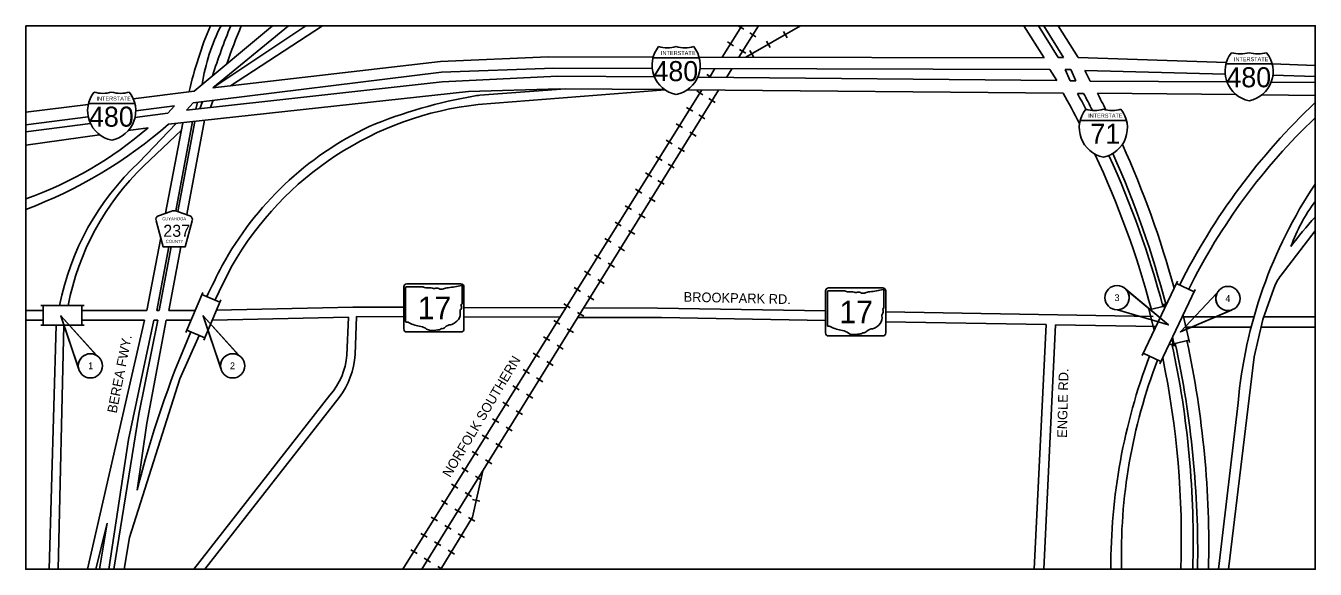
# Model space of a CAD drawing. Extents: x 0 to 1336, y 0 to 440.
# Drawn here: x 800 to 1336, y 188 to 413 of the extents above; entities that cross this region are included whole.
import ezdxf

# ---------------------------------------------------------------- set-up
doc = ezdxf.new("R2010")
doc.units = 0
for name, color, linetype in [('SH_Text', 7, 'Continuous'), ('SN_P_Text', 7, 'Continuous'), ('SN_X_Public', 7, 'Continuous')]:
    doc.layers.add(name, color=color, linetype=linetype)

msp = doc.modelspace()

# ---------------------------------------------------------------- linework, layer by layer
at = {"layer": 'SH_Text'}
for points in [[(1257.31, 303.98), (1274.97, 289.23), (1253.77, 295.49)], [(1301.11, 295.35), (1279.95, 286.31), (1295.15, 302.36)], [(821.92, 271.19), (814.58, 293), (829.38, 276.58)], [(881.02, 271.19), (873.69, 293), (888.48, 276.58)]]:
    msp.add_lwpolyline(points, dxfattribs=at)
for centre, major_axis in [((1253.63, 300.53), (3.65, 3.48)), ((1299.7, 300.2), (1.45, -4.83)), ((826.85, 272.21), (-4.93, -1.06)), ((885.96, 272.21), (-4.93, -1.06))]:
    msp.add_ellipse(centre, major_axis=major_axis, ratio=0.999122, start_param=3.977083, end_param=6.275668, dxfattribs=at)
at = {"layer": 'SN_P_Text'}
for p, q in [((869.93, 386.39), (902.5, 413.48)), ((877.75, 387.74), (909.24, 413.48)), ((916.35, 413.48), (877.75, 387.74)), ((885.07, 388.58), (923.29, 413.48)), ((1089.44, 400.45), (1097.57, 413.48)), ((1096.1, 413.48), (1098.45, 412.03)), ((1096.44, 400.43), (1104.53, 413.48)), ((1122.07, 413.48), (1099.23, 400.42)), ((1223.25, 400.11), (1214.87, 413.48)), ((1229.17, 400.32), (1220.91, 413.48)), ((1231.39, 400.32), (1223.13, 413.48)), ((1237.39, 400.32), (1229.13, 413.48)), ((1100.91, 410.5), (1103.51, 408.89)), ((1114.91, 411.14), (1116.43, 408.5)), ((1091.62, 406.82), (1094.21, 405.22)), ((1096.67, 403.69), (1099.26, 402.09)), ((1100.98, 403.18), (1102.5, 400.54)), ((1107.95, 407.16), (1109.47, 404.52)), ((877.75, 387.74), (972.38, 398.63)), ((972.38, 398.63), (1017.15, 400.63)), ((1017.15, 400.63), (1060.81, 400.52)), ((1079.87, 400.47), (1223.25, 400.11)), ((1231.39, 400.32), (1229.17, 400.32)), ((1237.39, 400.32), (1299.06, 398.27)), ((1318.11, 397.63), (1335.98, 397.04)), ((869.63, 381.53), (972.73, 394.16)), ((972.73, 394.16), (1019.53, 395.9)), ((1020.96, 392.6), (973.04, 390.21)), ((1019.53, 395.9), (1060.41, 395.77)), ((1020.96, 392.6), (1061.32, 392.25)), ((1079.28, 392.1), (1228.52, 390.81)), ((1080.25, 395.71), (1225.73, 395.26)), ((1083.13, 393.21), (1085, 392.05)), ((1084.2, 392.05), (1086.47, 395.69)), ((1091.21, 391.99), (1093.49, 395.67)), ((1228.52, 390.81), (1225.73, 395.26)), ((1234.16, 390.66), (1231.98, 395.26)), ((1231.98, 395.26), (1234.33, 395.26)), ((1236.51, 390.66), (1234.33, 395.26)), ((1240.18, 394.94), (1298.54, 393.43)), ((1240.18, 394.94), (1242.48, 390.54)), ((1318.39, 392.92), (1335.98, 392.46)), ((844.64, 383.2), (869.93, 386.39)), ((859.35, 372.58), (984, 386.12)), ((973.04, 390.21), (866.77, 378.43)), ((956.78, 187.73), (1080.94, 386.82)), ((964.61, 187.73), (1087.97, 386.76)), ((984, 386.12), (1021.85, 387.33)), ((988.1, 380.77), (1065.7, 386.85)), ((988.7, 384.61), (1024.39, 387.3)), ((1021.85, 387.33), (1065.56, 386.95)), ((1074.99, 386.87), (1231.16, 385.52)), ((1078.88, 386.4), (1081.47, 384.8)), ((1236.51, 390.66), (1234.16, 390.66)), ((1242.48, 390.54), (1299.3, 390.14)), ((1317.64, 390.02), (1335.98, 389.89)), ((799.98, 377.57), (825.97, 380.84)), ((866.77, 378.43), (869.63, 381.53)), ((870.66, 378.86), (871.4, 381.75)), ((872.29, 379.04), (873.42, 381.99)), ((876.83, 379.55), (877.88, 382.54)), ((1083.95, 383.26), (1086.54, 381.65)), ((1237.14, 385.38), (1239.7, 385.41)), ((1303.07, 384.89), (1245.42, 385.48)), ((1335.98, 384.55), (1313.78, 384.78)), ((825.95, 375.62), (799.98, 372.28)), ((845.36, 375.35), (858.97, 377.13)), ((861.83, 380.22), (845.69, 378.15)), ((858.97, 377.13), (861.83, 380.22)), ((1074.64, 379.59), (1077.23, 377.99)), ((1079.71, 376.45), (1082.3, 374.85)), ((799.98, 369.43), (826.84, 372.94)), ((850.81, 371.13), (842.6, 369.96)), ((847.04, 356.75), (862.48, 372.92)), ((849.08, 355.36), (864.68, 370.08)), ((858.04, 335.6), (865.29, 373.23)), ((862.31, 336.59), (869.32, 373.67)), ((863.18, 336.36), (870.25, 373.77)), ((866.91, 335.02), (874.32, 374.21)), ((1070.39, 372.79), (1072.98, 371.18)), ((830.6, 368.25), (799.98, 363.88)), ((1066.15, 365.98), (1068.74, 364.38)), ((1076.03, 369.29), (1078.62, 367.69)), ((1061.9, 359.17), (1064.49, 357.57)), ((1071.22, 362.83), (1073.81, 361.23)), ((1066.97, 356.03), (1069.56, 354.43)), ((1057.66, 352.36), (1060.25, 350.76)), ((1062.73, 349.22), (1065.32, 347.62)), ((1053.41, 345.56), (1056, 343.95)), ((1049.17, 338.75), (1051.76, 337.15)), ((1059.05, 342.06), (1061.64, 340.46)), ((1054.8, 335.26), (1057.39, 333.65)), ((1044.92, 331.94), (1047.51, 330.34)), ((1050.56, 328.45), (1053.15, 326.85)), ((1321.8, 309.84), (1335.98, 328.29)), ((850.28, 295.26), (856.09, 325.46)), ((854.5, 295.26), (859.49, 321.64)), ((855.42, 295.26), (860.4, 321.64)), ((859.4, 295.26), (864.39, 321.64)), ((1040.68, 325.14), (1043.27, 323.53)), ((1046.31, 321.64), (1048.9, 320.04)), ((1036.43, 318.33), (1039.02, 316.73)), ((1032.19, 311.52), (1034.78, 309.92)), ((1042.07, 314.84), (1044.66, 313.23)), ((1037.82, 308.03), (1040.41, 306.43)), ((1264.03, 276.56), (1278.7, 307.38)), ((1278.27, 306.48), (1285.63, 302.97)), ((866.52, 286.11), (873.56, 302.75)), ((873.17, 301.83), (880.68, 298.65)), ((1027.94, 304.71), (1030.53, 303.11)), ((1033.58, 301.22), (1036.17, 299.62)), ((1274.97, 289.23), (1257.28, 304.01)), ((1271.39, 273.06), (1286.06, 303.87)), ((1279.95, 286.31), (1295.15, 302.37)), ((1318.81, 304.33), (1314.27, 291.51)), ((807.19, 295.26), (799.98, 295.26)), ((806.19, 297.27), (824.26, 297.27)), ((807.19, 297.27), (807.2, 289.11)), ((823.26, 297.27), (823.26, 289.11)), ((823.26, 295.26), (850.28, 295.26)), ((854.5, 295.26), (855.42, 295.26)), ((859.4, 295.26), (870.4, 295.26)), ((874.03, 282.94), (881.07, 299.58)), ((935.88, 296.59), (879.27, 295.32)), ((935.88, 296.59), (957.11, 296.52)), ((982.11, 296.44), (1024.5, 296.31)), ((1023.7, 297.91), (1026.29, 296.3)), ((1031.89, 296.29), (1062.58, 296.19)), ((1062.58, 296.19), (1132.43, 295.02)), ((1274.97, 289.23), (1253.76, 295.49)), ((1268.98, 286.96), (1266.72, 296.43)), ((1266.95, 295.46), (1273.18, 296.94)), ((1273.37, 296.18), (1272.95, 297.92)), ((1273.64, 296.75), (1273.34, 298.01)), ((1273.57, 297.04), (1273.8, 297.09)), ((1279.95, 286.31), (1301.14, 295.37)), ((807.2, 291.15), (799.98, 291.15)), ((814.58, 293), (821.93, 271.15)), ((814.58, 293), (829.38, 276.57)), ((849.38, 291.14), (823.26, 291.12)), ((825.65, 187.73), (849.38, 291.14)), ((842.62, 241.58), (853.25, 291.14)), ((846.94, 252.2), (854.91, 291.14)), ((850.36, 248.39), (858.37, 291.15)), ((853.25, 291.14), (854.91, 291.14)), ((868.66, 291.15), (858.37, 291.15)), ((873.69, 293), (881.04, 271.15)), ((873.69, 293), (888.49, 276.57)), ((934.11, 292.47), (877.53, 291.2)), ((934.11, 292.47), (933.48, 276.69)), ((937.49, 292.65), (936.86, 276.87)), ((937.49, 292.65), (957.11, 292.59)), ((982.11, 292.51), (1022.05, 292.38)), ((1019.45, 291.1), (1022.04, 289.5)), ((1029.33, 294.41), (1031.92, 292.81)), ((1029.46, 292.36), (1064.18, 292.25)), ((1064.18, 292.25), (1132.43, 291.01)), ((1157.43, 294.61), (1268.64, 292.75)), ((1157.43, 290.56), (1224.13, 289.34)), ((1283.73, 281.9), (1281.03, 293.31)), ((1281.21, 292.55), (1310.5, 292.55)), ((1314.27, 291.51), (1310.61, 276.01)), ((1314.63, 292.55), (1335.98, 292.55)), ((806.2, 289.11), (824.27, 289.11)), ((812.68, 289.11), (809.77, 187.73)), ((815.85, 289.11), (813.43, 187.73)), ((864.06, 266.82), (872.08, 284.85)), ((866.91, 287.03), (874.42, 283.86)), ((1015.2, 284.29), (1017.8, 282.69)), ((1025.09, 287.61), (1027.68, 286)), ((1224.13, 289.34), (1219.21, 187.73)), ((1228.06, 289.27), (1223.14, 187.73)), ((1228.06, 289.27), (1269.69, 288.52)), ((1282.22, 288.3), (1309.35, 288.3)), ((1313.51, 288.3), (1335.98, 288.3)), ((1020.84, 280.8), (1023.43, 279.2)), ((1275.11, 280.88), (1276.91, 281.31)), ((1277.15, 280.34), (1276.38, 283.54)), ((1277.49, 280.42), (1276.63, 284.07)), ((1277.26, 281.39), (1283.5, 282.87)), ((1010.96, 277.49), (1013.55, 275.88)), ((1016.6, 273.99), (1019.19, 272.39)), ((1264.46, 277.46), (1271.82, 273.96)), ((1299.9, 187.73), (1310.61, 276.01)), ((1006.71, 270.68), (1009.31, 269.08)), ((843.16, 200.95), (864.06, 266.82)), ((1002.47, 263.87), (1005.06, 262.27)), ((1012.35, 267.19), (1014.94, 265.58)), ((926.37, 260.06), (869.9, 187.73)), ((930.23, 259.05), (874.37, 187.73)), ((1008.1, 260.38), (1010.7, 258.78)), ((836.53, 187.73), (846.94, 252.2)), ((998.22, 257.06), (1000.82, 255.46)), ((1003.86, 253.57), (1006.45, 251.97)), ((1303.94, 256.82), (1295.8, 187.73)), ((846.32, 220.62), (850.36, 248.39)), ((993.98, 250.26), (996.57, 248.65)), ((999.61, 246.76), (1002.21, 245.16)), ((834.55, 187.73), (842.62, 241.58)), ((989.73, 243.45), (992.33, 241.85)), ((985.49, 236.64), (988.08, 235.04)), ((995.37, 239.96), (997.96, 238.35)), ((991.12, 233.15), (993.72, 231.55)), ((981.24, 229.84), (983.84, 228.23)), ((985.65, 209.3), (989.91, 228.54)), ((986.88, 226.34), (989.47, 224.74)), ((977, 223.03), (979.59, 221.43)), ((972.75, 216.22), (975.35, 214.62)), ((982.63, 219.54), (985.23, 217.93)), ((985.7, 216.65), (988.66, 215.93)), ((968.51, 209.41), (971.1, 207.81)), ((972.53, 187.73), (985.65, 209.3)), ((978.39, 212.73), (980.98, 211.13)), ((984.02, 209.24), (986.62, 207.63)), ((829.14, 187.73), (833.87, 206.79)), ((833.87, 206.79), (830.66, 187.73)), ((974.14, 205.92), (976.74, 204.32)), ((840.81, 187.73), (843.16, 200.95)), ((964.26, 202.61), (966.86, 201)), ((969.9, 199.11), (972.49, 197.51)), ((979.78, 202.43), (982.37, 200.83)), ((960.02, 195.8), (962.61, 194.2)), ((975.53, 195.62), (978.13, 194.02)), ((965.65, 192.31), (968.25, 190.7)), ((971.29, 188.81), (973.05, 187.73))]:
    msp.add_line(p, q, dxfattribs=at)
msp.add_lwpolyline([(799.98, 413.48), (1335.98, 413.48), (1335.98, 187.73), (799.98, 187.73)], close=True, dxfattribs=at)
for centre in [(1253.63, 300.53), (1299.7, 300.2), (826.85, 272.21), (885.96, 272.21)]:
    msp.add_circle(centre, 5.04, dxfattribs=at)
for centre, radius, start, end in [((1024.07, 351.11), 160.01, 157.0585, 167.3544), ((953.3, 376.87), 80.92, 153.1009, 171.2226), ((1175.75, 295.13), 313.75, 157.838, 161.8717), ((1113.43, 318.45), 243.19, 156.9972, 160.9866), ((1002.75, 246.61), 134.95, 96.2321, 150.1214), ((1021.46, 181.98), 205.35, 99.7102, 112.5581), ((990.2, 364.67), 20, 94.3094, 99.7102), ((904.77, 199.73), 375.56, 27.4549, 29.6496), ((902.63, 199.67), 382.6, 27.9227, 29.0381), ((880.26, 194.77), 406.87, 26.8205, 27.9417), ((886.79, 197.44), 404.94, 26.5738, 27.6701), ((1520.6, 185.42), 269.36, 133.2685, 153.4506), ((1510.93, 191.16), 253.99, 133.5347, 153.6154), ((731.4, 519.62), 194.91, 290.6032, 311.0305), ((747.92, 489.68), 156.97, 289.3703, 310.954), ((1001.18, 248.65), 136.17, 115.4419, 151.3968), ((904.77, 199.73), 375.56, 14.8013, 25.2911), ((902.63, 199.67), 382.6, 14.7103, 24.7033), ((880.26, 194.77), 406.87, 14.6155, 24.0241), ((886.79, 197.44), 404.94, 15.3299, 24.315), ((921.98, 276.29), 109.95, 132.9663, 168.9997), ((925.49, 276.29), 109.95, 134.0189, 168.9997), ((1497.27, 239.79), 194.08, 146.2045, 174.9647), ((1394.44, 296.93), 72.92, 143.288, 160.0385), ((1426.77, 248.8), 124.53, 136.8061, 144.0968), ((1261.56, 116.6), 428.08, 152.5635, 154.4888), ((1265.66, 116.6), 428.08, 152.5635, 154.7028), ((1337.66, 297.66), 20, 142.4609, 160.4891), ((1261.56, 116.6), 428.08, 156.6405, 165.9362), ((902.63, 199.67), 382.6, 358.2115, 12.3041), ((880.26, 194.77), 406.87, 359.0088, 12.3108), ((886.79, 197.44), 404.94, 358.6261, 12.1509), ((905.47, 278.84), 28.09, 318.0595, 355.6093), ((904.32, 278.83), 32.6, 322.6409, 356.5519), ((1497.06, 188.76), 246.02, 159.1818, 180.2414), ((1480.74, 193.53), 225.34, 158.9175, 181.4769), ((904.77, 199.73), 375.56, 358.1683, 11.6532)]:
    msp.add_arc(centre, radius, start, end, dxfattribs=at)
at = {"layer": 'SN_X_Public'}
for p, q in [((1060.71, 400.18), (1079.95, 400.18)), ((1298.87, 397.62), (1318.11, 397.62)), ((826.07, 381.25), (845.3, 381.25)), ((1238.29, 374.17), (1257.53, 374.17)), ((855.19, 334.57), (860.23, 336.39)), ((863.1, 336.39), (868.14, 334.57)), ((957.89, 304.81), (957.89, 290.58)), ((964.99, 305.06), (958.13, 305.06)), ((981.33, 297.96), (981.33, 305.41)), ((1133.21, 303.14), (1133.21, 288.91)), ((1140.3, 303.38), (1133.44, 303.38)), ((1156.65, 296.29), (1156.65, 303.73)), ((981.33, 297.97), (981.33, 297.96)), ((1156.64, 296.29), (1156.65, 296.29))]:
    msp.add_line(p, q, dxfattribs=at)
for points in [[(869.2, 332.52), (866.17, 321.64), (857.15, 321.64), (854.13, 332.52), (854.13, 332.52)], [(958.36, 306.28), (980.86, 306.28)], [(957.11, 287.53), (957.11, 305.03)], [(982.11, 305.03), (982.11, 287.53)], [(1132.43, 285.86), (1132.43, 303.36)], [(1133.68, 304.61), (1156.18, 304.61)], [(1157.43, 303.36), (1157.43, 285.86)], [(980.86, 286.28), (958.36, 286.28)], [(1156.18, 284.61), (1133.68, 284.61)]]:
    msp.add_lwpolyline(points, dxfattribs=at)
for centre, radius, start, end in [((1072.83, 397.12), 12.5, 141.669, 258.463), ((1066.68, 416.82), 12.5, 253.0091, 286.9909), ((1073.99, 416.82), 12.5, 253.0091, 286.9909), ((1067.83, 397.12), 12.5, 281.537, 38.331), ((1310.99, 394.56), 12.5, 141.669, 258.463), ((1304.84, 414.27), 12.5, 253.0091, 286.9909), ((1312.15, 414.27), 12.5, 253.0091, 286.9909), ((1305.99, 394.56), 12.5, 281.537, 38.331), ((838.19, 378.19), 12.5, 141.669, 258.463), ((832.03, 397.9), 12.5, 253.0091, 286.9909), ((839.34, 397.9), 12.5, 253.0091, 286.9909), ((833.19, 378.19), 12.5, 281.537, 38.331), ((1250.41, 371.1), 12.5, 141.669, 258.463), ((1244.26, 390.81), 12.5, 253.0091, 286.9909), ((1251.56, 390.81), 12.5, 253.0091, 286.9909), ((1245.41, 371.1), 12.5, 281.537, 38.331), ((855.76, 332.98), 1.7, 109.7989, 195.5241), ((861.66, 332.4), 4.24, 70.2011, 109.7989), ((867.56, 332.98), 1.7, 344.4759, 70.2011), ((958.36, 305.03), 1.25, 90, 180), ((980.86, 305.03), 1.25, 0, 90), ((1133.68, 303.36), 1.25, 90, 180), ((1156.18, 303.36), 1.25, 0, 90), ((958.36, 287.53), 1.25, 180, 270), ((980.86, 287.53), 1.25, 270, 0), ((1133.68, 285.86), 1.25, 180, 270), ((1156.18, 285.86), 1.25, 270, 0)]:
    msp.add_arc(centre, radius, start, end, dxfattribs=at)
for centre, major_axis, start_param, end_param in [((972.98, 324.46), (24.85, 0), 4.814394, 5.042369), ((981.07, 305.44), (0.261, 0), 6.141152, 7.989035), ((958.16, 304.84), (0.272, 0), 1.712693, 3.28349), ((966.62, 306.71), (2.63, 0), 4.042523, 4.731795), ((967.5, 297.07), (9.45, 0), 1.404758, 1.657858), ((969.64, 304.91), (0.76, 0), 3.836095, 5.185415), ((970.76, 303.27), (1.58, 0), 0.950623, 2.079405), ((972.8, 305.53), (1.9, 0), 4.081561, 5.145723), ((976.15, 300.71), (5, 0), 1.699011, 2.107814), ((1133.48, 303.17), (0.272, 0), 1.712693, 3.28349), ((1141.94, 305.03), (2.63, 0), 4.042523, 4.731795), ((1142.81, 295.39), (9.45, 0), 1.404758, 1.657858), ((1144.96, 303.24), (0.76, 0), 3.836095, 5.185415), ((1146.07, 301.6), (1.58, 0), 0.950623, 2.079405), ((1148.11, 303.85), (1.9, 0), 4.081561, 5.145723), ((1151.47, 299.04), (5, 0), 1.699011, 2.107814), ((1148.3, 322.78), (24.85, 0), 4.814394, 5.042369), ((1156.39, 303.77), (0.261, 0), 6.141152, 7.989035), ((982.27, 294.85), (1.76, 0), 2.387724, 3.262537), ((981.27, 297.42), (0.404, 0), 1.883978, 3.671073), ((978.7, 296.48), (2.42, 0), 5.934695, 6.695948), ((981.05, 297.94), (0.279, 0), 5.05454, 6.418171), ((1156.58, 295.74), (0.404, 0), 1.883978, 3.671073), ((1154.02, 294.8), (2.42, 0), 5.934695, 6.695948), ((1156.37, 296.26), (0.279, 0), 5.05454, 6.418171), ((958.17, 290.55), (0.274, 0), 3.00124, 4.508301), ((958.21, 292), (2.09, 0), 4.665946, 4.897461), ((958.63, 289.76), (0.754, 0), 0.519207, 1.627899), ((968.15, 302.54), (17.95, 0), 4.195997, 4.488961), ((974.38, 293.9), (6.22, 0), 5.101752, 6.440018), ((1149.69, 292.23), (6.22, 0), 5.101752, 6.440018), ((1157.58, 293.17), (1.76, 0), 2.387724, 3.262537), ((962.8, 284.19), (5.62, 0), 0.823519, 1.323587), ((968.87, 289.69), (3.56, 0), 4.026481, 4.996735), ((970.93, 284.77), (2.93, 0), 1.495662, 1.94098), ((971.19, 288.62), (1.9, 0), 4.691044, 5.507374), ((972.91, 287.24), (0.535, 0), 1.147584, 2.315152), ((972.68, 289.2), (2.01, 0), 4.937069, 5.64225), ((977, 286.58), (3.4, 0), 1.647645, 2.488434), ((1133.48, 288.87), (0.274, 0), 3.00124, 4.508301), ((1133.52, 290.33), (2.09, 0), 4.665946, 4.897461), ((1133.95, 288.09), (0.754, 0), 0.519207, 1.627899), ((1143.46, 300.87), (17.95, 0), 4.195997, 4.488961), ((1138.11, 282.51), (5.62, 0), 0.823519, 1.323587), ((1144.19, 288.01), (3.56, 0), 4.026481, 4.996735), ((1146.25, 283.09), (2.93, 0), 1.495662, 1.94098), ((1146.51, 286.95), (1.9, 0), 4.691044, 5.507374), ((1148.22, 285.57), (0.535, 0), 1.147584, 2.315152), ((1148, 287.53), (2.01, 0), 4.937069, 5.64225), ((1152.31, 284.91), (3.4, 0), 1.647645, 2.488434)]:
    msp.add_ellipse(centre, major_axis=major_axis, ratio=0.8, start_param=start_param, end_param=end_param, dxfattribs=at)

# ---------------------------------------------------------------- texts
at = {"layer": 'SN_P_Text'}
for s, rotation, p in [('BROOKPARK RD.', 358.6723, (1073.4, 298.89)), ('BEREA FWY.', 78.8044, (837.71, 252.3)), ('NORFOLK SOUTHERN', 59.0973, (976.37, 225.57)), ('ENGLE RD.', 88.6723, (1232.74, 242.26))]:
    msp.add_text(s, height=4, rotation=rotation, dxfattribs=at).set_placement(p)
for s, p in [('3', (1252.54, 299.13)), ('4', (1298.63, 298.8)), ('1', (825.92, 270.81)), ('2', (884.86, 270.81))]:
    msp.add_text(s, height=2.8, dxfattribs=at).set_placement(p)
at = {"layer": 'SN_X_Public'}
for s, height, p in [('INTERSTATE', 1.667, (1064.02, 401.33)), ('480', 8.333, (1060.9, 390.49)), ('INTERSTATE', 1.667, (1302.18, 398.77)), ('480', 8.333, (1299.06, 387.94)), ('INTERSTATE', 1.667, (829.37, 382.4)), ('480', 8.333, (826.26, 371.57)), ('INTERSTATE', 1.667, (1241.6, 375.32)), ('71', 8.333, (1242.51, 364.48)), ('CUYAHOGA', 1.25, (856.73, 332.68)), ('237', 5, (857.13, 325.81)), ('COUNTY', 1.25, (858.13, 323.31)), ('17', 9.375, (962.91, 291.58)), ('17', 9.375, (1138.22, 289.91))]:
    msp.add_text(s, height=height, dxfattribs=at).set_placement(p)

doc.saveas('drawing.dxf')
